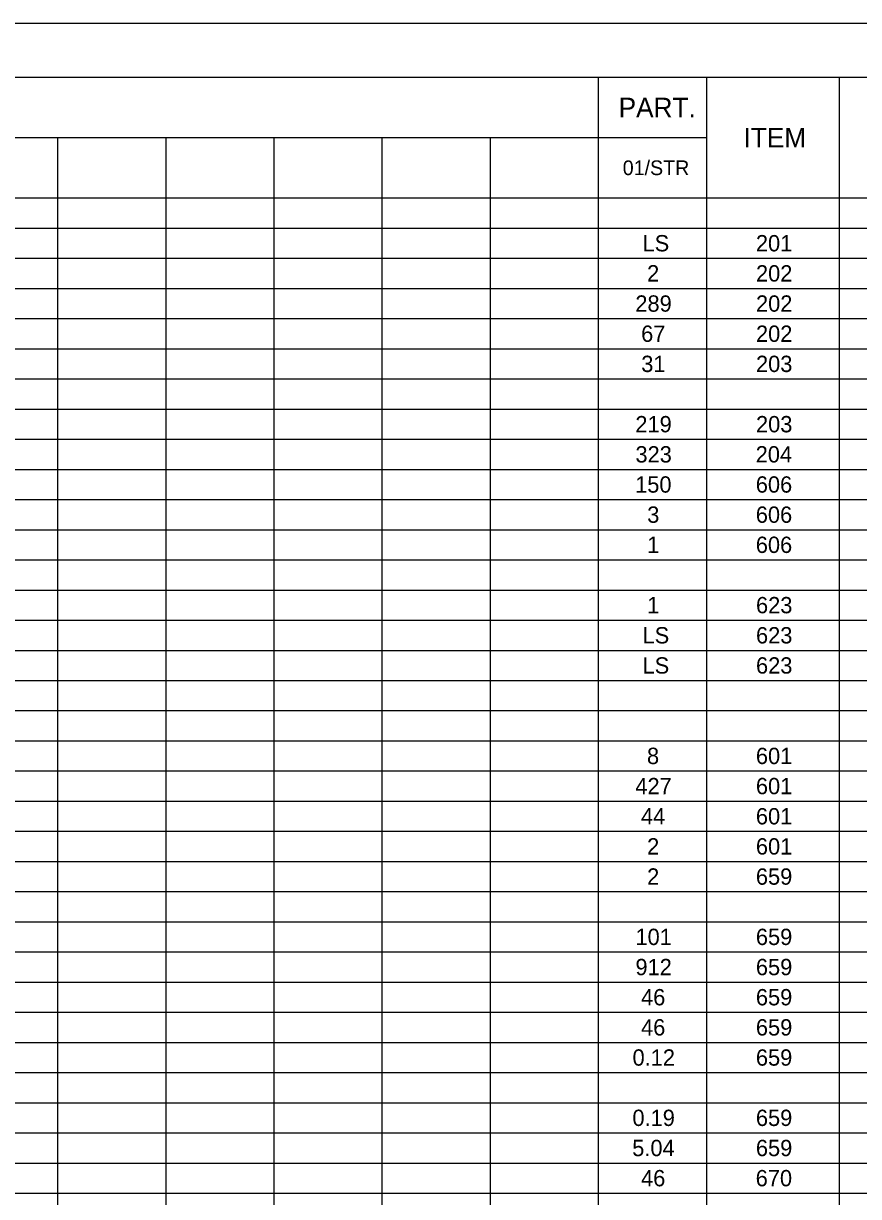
# Model space of a CAD drawing. Extents: x 0 to 34, y 0 to 22.
# Drawn here: x 9.22 to 16.98, y 11.11 to 22 of the extents above; entities that cross this region are included whole.
import ezdxf

# ---------------------------------------------------------------- set-up
doc = ezdxf.new("R2010")
doc.units = 0
for name, color, linetype in [('Default', 7, 'Continuous'), ('SH_Border', 7, 'Continuous'), ('SH_Cut_Line', 7, 'Continuous')]:
    doc.layers.add(name, color=color, linetype=linetype)

msp = doc.modelspace()

# ---------------------------------------------------------------- linework, layer by layer
at = {"layer": 'Default'}
for p, q in [((1.5, 21.5), (32, 21.5)), ((14.56, 21.5), (14.56, 0.5)), ((15.564, 21.5), (15.564, 0.5)), ((16.799, 21.5), (16.799, 0.5)), ((1.5, 20.94), (15.564, 20.94)), ((9.537, 20.94), (9.537, 0.5)), ((10.541, 20.94), (10.541, 0.5)), ((11.546, 20.94), (11.546, 0.5)), ((12.55, 20.94), (12.55, 0.5)), ((13.555, 20.94), (13.555, 0.5)), ((1.5, 20.38), (32, 20.38)), ((1.5, 20.1), (32, 20.1)), ((1.5, 19.82), (32, 19.82)), ((1.5, 19.54), (32, 19.54)), ((1.5, 19.26), (32, 19.26)), ((1.5, 18.98), (32, 18.98)), ((1.5, 18.7), (32, 18.7)), ((1.5, 18.42), (32, 18.42)), ((1.5, 18.14), (32, 18.14)), ((1.5, 17.86), (32, 17.86)), ((1.5, 17.58), (32, 17.58)), ((1.5, 17.3), (32, 17.3)), ((1.5, 17.02), (32, 17.02)), ((1.5, 16.74), (32, 16.74)), ((1.5, 16.46), (32, 16.46)), ((1.5, 16.18), (32, 16.18)), ((1.5, 15.9), (32, 15.9)), ((1.5, 15.62), (32, 15.62)), ((1.5, 15.34), (32, 15.34)), ((1.5, 15.06), (32, 15.06)), ((1.5, 14.78), (32, 14.78)), ((1.5, 14.5), (32, 14.5)), ((1.5, 14.22), (32, 14.22)), ((1.5, 13.94), (32, 13.94)), ((1.5, 13.66), (32, 13.66)), ((1.5, 13.38), (32, 13.38)), ((1.5, 13.1), (32, 13.1)), ((1.5, 12.82), (32, 12.82)), ((1.5, 12.54), (32, 12.54)), ((1.5, 12.26), (32, 12.26)), ((1.5, 11.98), (32, 11.98)), ((1.5, 11.7), (32, 11.7)), ((1.5, 11.42), (32, 11.42)), ((1.5, 11.14), (32, 11.14))]:
    msp.add_line(p, q, dxfattribs=at)
at = {"layer": 'SH_Border'}
msp.add_lwpolyline([(1.5, 21.5), (33.5, 21.5), (33.5, 0.5), (1.5, 0.5)], close=True, dxfattribs=at)
at = {"layer": 'SH_Cut_Line'}
msp.add_lwpolyline([(0, 0), (34, 0), (34, 22), (0, 22)], close=True, dxfattribs=at)

# ---------------------------------------------------------------- texts
at = {"layer": 'Default'}
for s, height, p in [('PART.', 0.1818, (14.749, 21.129)), ('ITEM', 0.1818, (15.91, 20.849)), ('01/STR', 0.1364, (14.787, 20.592)), ('LS', 0.1515, (14.971, 19.884)), ('201', 0.1515, (16.024, 19.884)), ('2', 0.152, (15.013, 19.604)), ('202', 0.1515, (16.025, 19.604)), ('289', 0.1515, (14.904, 19.324)), ('202', 0.1515, (16.025, 19.324)), ('67', 0.1515, (14.958, 19.044)), ('202', 0.1515, (16.025, 19.044)), ('31', 0.1515, (14.959, 18.764)), ('203', 0.1515, (16.025, 18.764)), ('219', 0.1515, (14.904, 18.204)), ('203', 0.1515, (16.025, 18.204)), ('323', 0.1515, (14.905, 17.924)), ('204', 0.1515, (16.022, 17.924)), ('150', 0.1515, (14.902, 17.644)), ('606', 0.1515, (16.023, 17.644)), ('3', 0.152, (15.014, 17.364)), ('606', 0.1515, (16.023, 17.364)), ('1', 0.152, (15.013, 17.084)), ('606', 0.1515, (16.023, 17.084)), ('1', 0.152, (15.013, 16.524)), ('623', 0.1515, (16.025, 16.524)), ('LS', 0.1515, (14.971, 16.244)), ('623', 0.1515, (16.025, 16.244)), ('LS', 0.1515, (14.971, 15.964)), ('623', 0.1515, (16.025, 15.964)), ('8', 0.152, (15.012, 15.124)), ('601', 0.1515, (16.024, 15.124)), ('427', 0.1515, (14.904, 14.844)), ('601', 0.1515, (16.024, 14.844)), ('44', 0.1515, (14.956, 14.564)), ('601', 0.1515, (16.024, 14.564)), ('2', 0.152, (15.013, 14.284)), ('601', 0.1515, (16.024, 14.284)), ('2', 0.152, (15.013, 14.004)), ('659', 0.1515, (16.024, 14.004)), ('101', 0.1515, (14.905, 13.444)), ('659', 0.1515, (16.024, 13.444)), ('912', 0.1515, (14.905, 13.164)), ('659', 0.1515, (16.024, 13.164)), ('46', 0.1515, (14.957, 12.884)), ('659', 0.1515, (16.024, 12.884)), ('46', 0.1515, (14.957, 12.604)), ('659', 0.1515, (16.024, 12.604)), ('0.12', 0.1515, (14.878, 12.324)), ('659', 0.1515, (16.024, 12.324)), ('0.19', 0.1515, (14.877, 11.764)), ('659', 0.1515, (16.024, 11.764)), ('5.04', 0.1515, (14.875, 11.484)), ('659', 0.1515, (16.024, 11.484)), ('46', 0.1515, (14.957, 11.204)), ('670', 0.1515, (16.022, 11.204))]:
    msp.add_text(s, height=height, dxfattribs=at).set_placement(p)

doc.saveas('drawing.dxf')
